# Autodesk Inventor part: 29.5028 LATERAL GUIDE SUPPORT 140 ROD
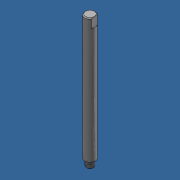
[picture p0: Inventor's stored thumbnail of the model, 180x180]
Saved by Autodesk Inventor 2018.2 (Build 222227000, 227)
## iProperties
Created: 2007-07
Part Number: 29.5028 LATERAL GUIDE SUPPORT 140 ROD
Material: Stainless Steel
Document SubType Name: Modeling
Designer: Andy Moles
Density: 8.08 g/cm^3
Appearance: Steel
Author: Andy Moles
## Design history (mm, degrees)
sketch "Sketch1"
  geometry: C1 r 6 at (0, 0); 1 further point
  constraints: 1 centre point, 1 coincident
  dimensions: "d0" = 12 diameter of C1
extrude "Extrusion1" new body sketch "Sketch1" distance "d1" = 140; taper "d2" = 0 deg
chamfer "Chamfer1" distance "d3" = 1; stored, may be unused: second distance "d4" = 2, angle "d5" = 45 deg
sketch "Sketch2"
  geometry: C1 r 6 at (0, 0) reference; C2 r 4 at (0, 0)
  constraints: 1 centre point, 1 coincident
  dimensions: "d6" = 8 diameter of C2
extrude "Extrusion2" join sketch "Sketch2" distance "d7" = 8; taper "d8" = 0 deg
thread "Thread1" dims "d9" = 10, "d10" = 0
chamfer "Chamfer2" distance "d11" = 0.5; stored, may be unused: second distance "d12" = 2, angle "d13" = 45 deg
sketch "Sketch3"
  geometry: L1 (-26.253, 5)-(-5, 5); L2 (-5, 5)-(-5, -5); L3 (-5, -5)-(-26.253, -5); L4 (-26.253, -5)-(-26.253, 5); L5 (10, 5)-(5, 5); L6 (5, 5)-(5, -5); L7 (5, -5)-(10, -5); L8 (10, -5)-(10, 5); C1 r 5 at (0, 0) reference
  constraints: 16 end point, 4 parallel, 2 horizontal, 2 perpendicular, 1 horizontal alignment, 1 point on line
  dimensions: "d15" = 10 distance of L7.end L5.start; "d16" = 5 distance from line of L5 C1.centre; "d17" = 5 distance of L6.end L7.end; "d18" = 5 distance from line of L6 C1.centre; "d20" = 10 distance between parallel lines of L6 L2
extrude "Extrusion3" cut sketch "Sketch3" distance "d21" = 10; taper "d22" = 0 deg
body "Solid1"
